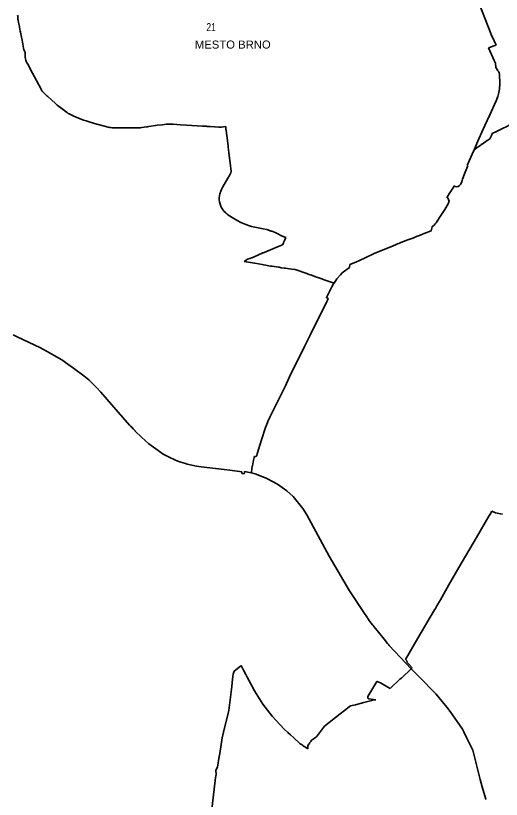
# Model space of a CAD drawing. Extents: x -610940 to -588976, y -1170376 to -1149800.
# Drawn here: x -599073 to -597562, y -1163066 to -1160628 of the extents above; entities that cross this region are included whole.
import ezdxf

# ---------------------------------------------------------------- set-up
doc = ezdxf.new("R2010")
doc.units = 0
doc.header["$LTSCALE"] = 10
doc.layers.add('54', color=7, linetype='Continuous', lineweight=35)
doc.layers.add('55', color=7, linetype='Continuous')
doc.layers.add('56', color=7, linetype='Continuous')

msp = doc.modelspace()

# ---------------------------------------------------------------- linework, layer by layer
at = {"layer": '54'}
for p, q in [((-597594.88, -1160683.07), (-597668.25, -1160495.45)), ((-599066.41, -1160629.92), (-599066.9, -1160626.17)), ((-599066.35, -1160633.96), (-599066.41, -1160629.92)), ((-599066.06, -1160638.29), (-599066.35, -1160633.96)), ((-599065.55, -1160642.13), (-599066.06, -1160638.29)), ((-599064.01, -1160649.25), (-599065.55, -1160642.13)), ((-599062.11, -1160657.95), (-599064.01, -1160649.25)), ((-599061.45, -1160661.37), (-599062.11, -1160657.95)), ((-599061.2, -1160663.36), (-599061.45, -1160661.37)), ((-599061.2, -1160663.36), (-599058.69, -1160676.02)), ((-599058.06, -1160679.43), (-599058.69, -1160676.02)), ((-599058.06, -1160679.43), (-599054.94, -1160694.74)), ((-599053.2, -1160704.32), (-599054.94, -1160694.74)), ((-599048.46, -1160728.59), (-599053.2, -1160704.32)), ((-597599.24, -1160726.56), (-597590.59, -1160723.51)), ((-597590.59, -1160723.51), (-597588.74, -1160722.86)), ((-597588.74, -1160722.86), (-597578.55, -1160719.28)), ((-599045.09, -1160738.12), (-599046.58, -1160735.24)), ((-599043.25, -1160742.45), (-599045.09, -1160738.12)), ((-599043.48, -1160750.77), (-599043.22, -1160747.53)), ((-599043.22, -1160747.53), (-599043.25, -1160742.45)), ((-597602.26, -1160727.62), (-597599.24, -1160726.56)), ((-599043.73, -1160755.78), (-599043.48, -1160750.77)), ((-599043.48, -1160758.32), (-599043.73, -1160755.78)), ((-599041.47, -1160766.34), (-599043.48, -1160758.32)), ((-599041.47, -1160766.34), (-599038.86, -1160772.13)), ((-599036.82, -1160776.06), (-599038.86, -1160772.13)), ((-599035.61, -1160778.39), (-599036.82, -1160776.06)), ((-599020.75, -1160807.03), (-599035.61, -1160778.39)), ((-599020.75, -1160807.03), (-599008.15, -1160829.7)), ((-599006.87, -1160832.11), (-599008.15, -1160829.7)), ((-598993.88, -1160856.59), (-599006.87, -1160832.11)), ((-598992.68, -1160858.85), (-598993.88, -1160856.59)), ((-598991.16, -1160861.71), (-598992.68, -1160858.85)), ((-598989.61, -1160863.67), (-598991.16, -1160861.71)), ((-598979.64, -1160873.91), (-598989.61, -1160863.67)), ((-597569.78, -1160867.25), (-597573.07, -1160879.91)), ((-598974.58, -1160878.03), (-598979.64, -1160873.91)), ((-598972.51, -1160879.73), (-598974.58, -1160878.03)), ((-598961.61, -1160890.04), (-598972.51, -1160879.73)), ((-598949.57, -1160901.32), (-598961.61, -1160890.04)), ((-597578.35, -1160892.94), (-597573.07, -1160879.91)), ((-598943.73, -1160906.84), (-598949.57, -1160901.32)), ((-598928.76, -1160918.03), (-598943.73, -1160906.84)), ((-598920.37, -1160924.27), (-598928.76, -1160918.03)), ((-598919.86, -1160924.7), (-598920.37, -1160924.27)), ((-598919.34, -1160925.06), (-598919.86, -1160924.7)), ((-598915.25, -1160928.11), (-598919.34, -1160925.06)), ((-598913.16, -1160929.48), (-598915.25, -1160928.11)), ((-598910.7, -1160931.18), (-598913.16, -1160929.48)), ((-598909.25, -1160932.14), (-598910.7, -1160931.18)), ((-598909.25, -1160932.14), (-598906.96, -1160933.05)), ((-598827.31, -1160962.99), (-598844.53, -1160958.1)), ((-598785.6, -1160974.72), (-598827.31, -1160962.99)), ((-598616.44, -1160967.17), (-598632.33, -1160969.03)), ((-598604.62, -1160966), (-598616.44, -1160967.17)), ((-598595.76, -1160965.71), (-598604.62, -1160966)), ((-598582.8, -1160965.72), (-598595.76, -1160965.71)), ((-598560.6, -1160967.14), (-598582.8, -1160965.72)), ((-598541.24, -1160968.18), (-598560.6, -1160967.14)), ((-598751.6, -1160976.39), (-598758.82, -1160977.15)), ((-598714.94, -1160976.93), (-598751.6, -1160976.39)), ((-598706.76, -1160976.86), (-598714.94, -1160976.93)), ((-598701.3, -1160976.83), (-598706.76, -1160976.86)), ((-598701.3, -1160976.83), (-598699.53, -1160976.82)), ((-598695.09, -1160976.8), (-598699.53, -1160976.82)), ((-598684.29, -1160976.62), (-598695.09, -1160976.8)), ((-598680.17, -1160976.07), (-598684.29, -1160976.62)), ((-598666.2, -1160974.2), (-598680.17, -1160976.07)), ((-598662.52, -1160973.72), (-598666.2, -1160974.2)), ((-598658.71, -1160973.12), (-598662.52, -1160973.72)), ((-598651.76, -1160972.06), (-598658.71, -1160973.12)), ((-598651.29, -1160971.93), (-598651.76, -1160972.06)), ((-598637.78, -1160969.85), (-598651.29, -1160971.93)), ((-598632.33, -1160969.03), (-598637.78, -1160969.85)), ((-598491.86, -1160971.37), (-598541.24, -1160968.18)), ((-598482.05, -1160972.03), (-598491.86, -1160971.37)), ((-598479.64, -1160972.19), (-598482.05, -1160972.03)), ((-598479.38, -1160972.21), (-598479.64, -1160972.19)), ((-598467.53, -1160973.01), (-598477.17, -1160972.36)), ((-598441.23, -1160974.45), (-598467.53, -1160973.01)), ((-598439.2, -1160974.55), (-598441.23, -1160974.45)), ((-598433.56, -1160974.83), (-598439.2, -1160974.55)), ((-598432.71, -1160974.7), (-598433.56, -1160974.83)), ((-598419.88, -1160973.04), (-598432.71, -1160974.7)), ((-598419.39, -1160975.88), (-598419.88, -1160973.04)), ((-598418.8, -1160981.9), (-598419.39, -1160975.88)), ((-598418.52, -1160983.89), (-598418.8, -1160981.9)), ((-598417.4, -1160993.06), (-598418.52, -1160983.89)), ((-598415.42, -1161008.49), (-598417.4, -1160993.06)), ((-598412.4, -1161034.23), (-598415.42, -1161008.49)), ((-597605.17, -1161015.95), (-597605.87, -1161016.4)), ((-598412.05, -1161036.82), (-598412.4, -1161034.23)), ((-598409.66, -1161054.09), (-598412.05, -1161036.82)), ((-597638.31, -1161038.82), (-597646.84, -1161045.22)), ((-597625.39, -1161029.41), (-597638.31, -1161038.82)), ((-597625.07, -1161029.18), (-597625.39, -1161029.41)), ((-597622.45, -1161027.58), (-597625.07, -1161029.18)), ((-598409.43, -1161056.18), (-598409.66, -1161054.09)), ((-598406.02, -1161085.51), (-598409.43, -1161056.18)), ((-598402.71, -1161112.81), (-598406.02, -1161085.51)), ((-598403.72, -1161117.01), (-598402.71, -1161112.81)), ((-597666.62, -1161094.84), (-597674.32, -1161114.99)), ((-597668.64, -1161094.03), (-597666.62, -1161094.84)), ((-598428.16, -1161160.61), (-598412.8, -1161133.51)), ((-598412.8, -1161133.51), (-598408.02, -1161125.63)), ((-598408.02, -1161125.63), (-598403.83, -1161117.31)), ((-598403.83, -1161117.31), (-598403.72, -1161117.01)), ((-597674.32, -1161114.99), (-597682.74, -1161136.59)), ((-598432.71, -1161169.23), (-598428.16, -1161160.61)), ((-597705.96, -1161159.46), (-597709.02, -1161157.86)), ((-598438.75, -1161188.27), (-598437.72, -1161182.67)), ((-598437.72, -1161182.67), (-598434.79, -1161173.45)), ((-598434.79, -1161173.45), (-598432.71, -1161169.23)), ((-598439.53, -1161194.7), (-598438.75, -1161188.27)), ((-598439.46, -1161200.48), (-598439.53, -1161194.7)), ((-598439.31, -1161207.09), (-598439.46, -1161200.48)), ((-598436.29, -1161217.76), (-598439.31, -1161207.09)), ((-598433.46, -1161223.74), (-598436.29, -1161217.76)), ((-598430.06, -1161230.26), (-598433.46, -1161223.74)), ((-598425.02, -1161236.55), (-598430.06, -1161230.26)), ((-598419.57, -1161241.87), (-598425.02, -1161236.55)), ((-598415.03, -1161245.67), (-598419.57, -1161241.87)), ((-598410.36, -1161249.19), (-598415.03, -1161245.67)), ((-598408, -1161250.49), (-598410.36, -1161249.19)), ((-598399.55, -1161255.76), (-598408, -1161250.49)), ((-598381.81, -1161266.18), (-598399.55, -1161255.76)), ((-598372.79, -1161270.99), (-598381.81, -1161266.18)), ((-598356.77, -1161277.36), (-598372.79, -1161270.99)), ((-598345.28, -1161281.54), (-598356.77, -1161277.36)), ((-598339.08, -1161283.42), (-598345.28, -1161281.54)), ((-598328.7, -1161286), (-598339.08, -1161283.42)), ((-598318.55, -1161287.95), (-598328.7, -1161286)), ((-598302.68, -1161291.04), (-598318.55, -1161287.95)), ((-598291.51, -1161293.62), (-598302.68, -1161291.04)), ((-598277.82, -1161297.99), (-598291.51, -1161293.62)), ((-598276.21, -1161298.8), (-598277.82, -1161297.99)), ((-598266.17, -1161303.05), (-598276.21, -1161298.8)), ((-598257.7, -1161307.04), (-598266.17, -1161303.05)), ((-598246.13, -1161312.49), (-598257.7, -1161307.04)), ((-598232.89, -1161318.61), (-598246.13, -1161312.49)), ((-598239.72, -1161334.14), (-598235.75, -1161325.87)), ((-598235.75, -1161325.87), (-598235.54, -1161325.32)), ((-598235.54, -1161325.32), (-598232.89, -1161318.61)), ((-598280.61, -1161356.28), (-598287.51, -1161359.22)), ((-598280.61, -1161356.28), (-598280.13, -1161356.14)), ((-598265.6, -1161350.06), (-598280.13, -1161356.14)), ((-598265.6, -1161350.06), (-598258.04, -1161346.97)), ((-598258.04, -1161346.97), (-598250.56, -1161343.85)), ((-598245.9, -1161341.95), (-598250.56, -1161343.85)), ((-598245.9, -1161341.95), (-598243.24, -1161340.68)), ((-598243.24, -1161340.68), (-598242.17, -1161339.71)), ((-598242.17, -1161339.71), (-598239.89, -1161334.82)), ((-598239.89, -1161334.82), (-598239.72, -1161334.14)), ((-597898.48, -1161343.76), (-597957.95, -1161368.31)), ((-598344.42, -1161383.07), (-598339.84, -1161381.57)), ((-598339.84, -1161381.57), (-598338, -1161380.97)), ((-598338, -1161380.97), (-598336.13, -1161380.24)), ((-598336.13, -1161380.24), (-598333.04, -1161379.16)), ((-598333.04, -1161379.16), (-598304.34, -1161366.26)), ((-598304.34, -1161366.26), (-598303.43, -1161365.96)), ((-598303.43, -1161365.96), (-598300.2, -1161364.58)), ((-598300.2, -1161364.58), (-598298.43, -1161363.84)), ((-598298.43, -1161363.84), (-598289.81, -1161360.2)), ((-598287.51, -1161359.22), (-598289.81, -1161360.2)), ((-598362.34, -1161392.74), (-598360.85, -1161391.58)), ((-598356.07, -1161393.6), (-598362.34, -1161392.74)), ((-598360.85, -1161391.58), (-598360.44, -1161391.82)), ((-598360.44, -1161391.82), (-598356.22, -1161388.78)), ((-598356.52, -1161388.45), (-598354.77, -1161387.14)), ((-598356.22, -1161388.78), (-598356.52, -1161388.45)), ((-598355.02, -1161393.73), (-598356.07, -1161393.6)), ((-598335.8, -1161397.11), (-598355.02, -1161393.73)), ((-598354.77, -1161387.14), (-598351.73, -1161385.95)), ((-598351.73, -1161385.95), (-598344.42, -1161383.07)), ((-598302.37, -1161403.12), (-598306.73, -1161402.37)), ((-598302.37, -1161403.12), (-598294.34, -1161404.4)), ((-598291.13, -1161404.91), (-598294.34, -1161404.4)), ((-598279.9, -1161406.94), (-598291.13, -1161404.91)), ((-598275.47, -1161407.46), (-598279.9, -1161406.94)), ((-598274.71, -1161407.57), (-598275.47, -1161407.46)), ((-598255.68, -1161410.48), (-598274.71, -1161407.57)), ((-598237.41, -1161413.2), (-598246.09, -1161412.28)), ((-598233.16, -1161413.52), (-598237.41, -1161413.2)), ((-598214.91, -1161416.32), (-598233.16, -1161413.52)), ((-598203.69, -1161418.04), (-598214.91, -1161416.32)), ((-598164.3, -1161431.63), (-598203.69, -1161418.04)), ((-598163.89, -1161431.89), (-598164.3, -1161431.63)), ((-598153.04, -1161435.74), (-598163.89, -1161431.89)), ((-598142.48, -1161439.35), (-598149.9, -1161436.71)), ((-598137.26, -1161441.06), (-598142.48, -1161439.35)), ((-598120.77, -1161446.88), (-598126.59, -1161444.89)), ((-598112.95, -1161449.52), (-598120.77, -1161446.88)), ((-598107.02, -1161451.62), (-598112.95, -1161449.52)), ((-598082.65, -1161460.09), (-598107.02, -1161451.62)), ((-598089.02, -1161471.3), (-598083.94, -1161462.19)), ((-598082.65, -1161460.09), (-598083.94, -1161462.19)), ((-598102.06, -1161511.05), (-598105.1, -1161517.25)), ((-599080.75, -1161621.2), (-599065.94, -1161628.12)), ((-599065.94, -1161628.12), (-598998.09, -1161660.51)), ((-598998.09, -1161660.51), (-598974.99, -1161672.34)), ((-598974.99, -1161672.34), (-598953.07, -1161685.05)), ((-598953.07, -1161685.05), (-598929.76, -1161698.95)), ((-598929.76, -1161698.95), (-598910.52, -1161712.03)), ((-598910.52, -1161712.03), (-598888.91, -1161727.38)), ((-598888.91, -1161727.38), (-598861.19, -1161748.52)), ((-598861.19, -1161748.52), (-598845.68, -1161761.08)), ((-598845.68, -1161761.08), (-598825.17, -1161781.28)), ((-598821.65, -1161784.92), (-598825.17, -1161781.28)), ((-598821.65, -1161784.92), (-598808.06, -1161799.42)), ((-598808.06, -1161799.42), (-598788.14, -1161822.37)), ((-598788.14, -1161822.37), (-598718.78, -1161901.85)), ((-598718.78, -1161901.85), (-598718.44, -1161902.25)), ((-598718.44, -1161902.25), (-598718.11, -1161902.63)), ((-598703.84, -1161917.32), (-598701.26, -1161919.92)), ((-598293.13, -1161902.29), (-598295.82, -1161909.22)), ((-598701.26, -1161919.92), (-598700.98, -1161920.26)), ((-598700.98, -1161920.26), (-598681.1, -1161939.74)), ((-598681.1, -1161939.74), (-598658.35, -1161959.86)), ((-598658.35, -1161959.86), (-598630.16, -1161981.32)), ((-598630.16, -1161981.32), (-598613.97, -1161991.76)), ((-598613.97, -1161991.76), (-598595.97, -1162001.6)), ((-598595.97, -1162001.6), (-598578.01, -1162010.1)), ((-598578.01, -1162010.1), (-598568.51, -1162013.74)), ((-598559.34, -1162017.25), (-598568.51, -1162013.74)), ((-598330.34, -1161999.7), (-598330.87, -1162001.34)), ((-598330.42, -1161999.13), (-598330.34, -1161999.7)), ((-598330.42, -1161999.13), (-598329.17, -1161999.67)), ((-598327.84, -1161999.87), (-598329.17, -1161999.67)), ((-598327.84, -1161999.87), (-598326.6, -1161999.69)), ((-598326.6, -1161999.69), (-598325.46, -1161999.37)), ((-598324.63, -1161998.8), (-598325.46, -1161999.37)), ((-598324.63, -1161998.8), (-598323.76, -1161998.16)), ((-598323.76, -1161998.16), (-598323.03, -1161997.13)), ((-598322.64, -1161996.12), (-598323.03, -1161997.13)), ((-598559.34, -1162017.25), (-598544.7, -1162021.54)), ((-598539.94, -1162022.93), (-598544.7, -1162021.54)), ((-598539.94, -1162022.93), (-598510.84, -1162029.39)), ((-598510.84, -1162029.39), (-598496.11, -1162031.78)), ((-598496.11, -1162031.78), (-598406.5, -1162041.96)), ((-598406.5, -1162041.96), (-598368.98, -1162046.88)), ((-598369.12, -1162047.84), (-598369.89, -1162052.52)), ((-598369.89, -1162052.52), (-598362.27, -1162053.87)), ((-598369.04, -1162047.3), (-598369.12, -1162047.84)), ((-598368.98, -1162046.88), (-598369.04, -1162047.3)), ((-598362.27, -1162053.87), (-598361.52, -1162048.88)), ((-598361.52, -1162048.88), (-598361.43, -1162048.3)), ((-598361.43, -1162048.3), (-598361.36, -1162047.8)), ((-598361.36, -1162047.8), (-598361.18, -1162046.53)), ((-598361.18, -1162046.53), (-598340.53, -1162050.35)), ((-598340.45, -1162049.97), (-598340.53, -1162050.35)), ((-597593.41, -1162172.45), (-597591.66, -1162169.43)), ((-597591.66, -1162169.43), (-597580.73, -1162174.42)), ((-597580.73, -1162174.42), (-597580.77, -1162174.72)), ((-598097.78, -1162309.19), (-598034.29, -1162417.39)), ((-597757.93, -1162455.57), (-597756.73, -1162453.43)), ((-597751.94, -1162445.17), (-597756.73, -1162453.43)), ((-597763.13, -1162464.52), (-597757.93, -1162455.57)), ((-597773.31, -1162482.07), (-597821.58, -1162564.89)), ((-597961.3, -1162525.5), (-597954.6, -1162533.5)), ((-597859.96, -1162631.03), (-597821.58, -1162564.89)), ((-597855.03, -1162636.18), (-597856.1, -1162639.64)), ((-597849.98, -1162646.15), (-597856.1, -1162639.64)), ((-597839.47, -1162657.18), (-597849.98, -1162646.15)), ((-598396.11, -1162676.68), (-598393.2, -1162667.95)), ((-598393.2, -1162667.95), (-598373.94, -1162652.35)), ((-598373.94, -1162652.35), (-598371.38, -1162650.24)), ((-598371.38, -1162650.24), (-598363.92, -1162664.78)), ((-598357.33, -1162677.85), (-598363.92, -1162664.78)), ((-597867.03, -1162683.19), (-597848.21, -1162665.42)), ((-597848.21, -1162665.42), (-597842.74, -1162660.07)), ((-598396.11, -1162676.68), (-598398.15, -1162692.85)), ((-598353.06, -1162686.32), (-598357.33, -1162677.85)), ((-598347.98, -1162695.71), (-598353.06, -1162686.32)), ((-598330.19, -1162728.59), (-598347.98, -1162695.71)), ((-597908.11, -1162721.5), (-597877.92, -1162692.82)), ((-597877.92, -1162692.82), (-597877.74, -1162692.74)), ((-597877.74, -1162692.74), (-597875.19, -1162690.71)), ((-597875.19, -1162690.71), (-597873.21, -1162689)), ((-597873.21, -1162689), (-597867.03, -1162683.19)), ((-597977.15, -1162746.49), (-597949.32, -1162699.43)), ((-597949.32, -1162699.43), (-597948.83, -1162699.65)), ((-597938.52, -1162704.22), (-597948.83, -1162699.65)), ((-598330.19, -1162728.59), (-598304.1, -1162770.27)), ((-597977.76, -1162751.42), (-597977.15, -1162746.49)), ((-598304.1, -1162770.27), (-598275.12, -1162807.77)), ((-598016.39, -1162771.94), (-597989.96, -1162765.29)), ((-597989.96, -1162765.29), (-597960.77, -1162758.18)), ((-597974.64, -1162753.6), (-597977.76, -1162751.42)), ((-597952.16, -1162756.86), (-597974.64, -1162753.6)), ((-597960.77, -1162758.18), (-597952.16, -1162756.86)), ((-598411.49, -1162797.71), (-598410.4, -1162790.07)), ((-598046.03, -1162786.56), (-598067.86, -1162803.46)), ((-598034.5, -1162777.64), (-598046.03, -1162786.56)), ((-598034.5, -1162777.64), (-598031.25, -1162775.8)), ((-598031.25, -1162775.8), (-598026.05, -1162774.27)), ((-598026.05, -1162774.27), (-598016.39, -1162771.94)), ((-597731.79, -1162778.94), (-597720.92, -1162792.47)), ((-597720.92, -1162792.47), (-597683.2, -1162847.84)), ((-598426.18, -1162857.33), (-598411.49, -1162797.71)), ((-598275.12, -1162807.77), (-598237.38, -1162848.22)), ((-598112.37, -1162838.49), (-598077.66, -1162811.09)), ((-598077.66, -1162811.09), (-598073.87, -1162808.11)), ((-598073.87, -1162808.11), (-598067.86, -1162803.46)), ((-598137.67, -1162871.26), (-598112.37, -1162838.49)), ((-598430.61, -1162874.56), (-598426.18, -1162857.33)), ((-598237.38, -1162848.22), (-598226.45, -1162858.19)), ((-598217.84, -1162865.92), (-598226.45, -1162858.19)), ((-598217.73, -1162866.02), (-598217.84, -1162865.92)), ((-598208.8, -1162874.17), (-598217.73, -1162866.02)), ((-597683.2, -1162847.84), (-597679.28, -1162855.81)), ((-597679.28, -1162855.81), (-597670.61, -1162873.35)), ((-598430.61, -1162874.56), (-598438.09, -1162923.19)), ((-598187.67, -1162893.45), (-598208.8, -1162874.17)), ((-598187.67, -1162893.45), (-598182.28, -1162897.03)), ((-598163.92, -1162898.96), (-598160.25, -1162893.03)), ((-598160.25, -1162893.03), (-598159.44, -1162892.11)), ((-598159.44, -1162892.11), (-598158.52, -1162890.58)), ((-598158.52, -1162890.58), (-598155.17, -1162885.83)), ((-598155.17, -1162885.83), (-598153.45, -1162883.38)), ((-598153.45, -1162883.38), (-598147.19, -1162878.93)), ((-598143.42, -1162875.92), (-598147.19, -1162878.93)), ((-598143.42, -1162875.92), (-598137.67, -1162871.26)), ((-597650.96, -1162912.75), (-597670.61, -1162873.35)), ((-598182.28, -1162897.03), (-598179.2, -1162899.05)), ((-598179.2, -1162899.05), (-598175.28, -1162901.64)), ((-598175.28, -1162901.64), (-598171.61, -1162904.06)), ((-598171.61, -1162904.06), (-598163.68, -1162909.29)), ((-598163.68, -1162909.29), (-598163.92, -1162898.96)), ((-598450.14, -1162975.68), (-598444.66, -1162965.91)), ((-598450.4, -1162994.49), (-598448.81, -1162989.08)), ((-598448.81, -1162989.08), (-598450.14, -1162975.68)), ((-598464.95, -1163115.09), (-598451.06, -1162998.14)), ((-598451.06, -1162998.14), (-598450.4, -1162994.49)), ((-597613.73, -1163055.42), (-597622.06, -1163027.57)), ((-597613.73, -1163055.42), (-597610.45, -1163066.2)), ((-597610.45, -1163066.2), (-597609.87, -1163066.21))]:
    msp.add_line(p, q, dxfattribs=at)
for points in [[(-597578.55, -1160719.28), (-597579.64, -1160717.36), (-597584.97, -1160706.4), (-597593.42, -1160686.94), (-597594.88, -1160683.07)], [(-599046.58, -1160735.24), (-599047.83, -1160732.94), (-599048.46, -1160728.59)], [(-597573.42, -1160798.47), (-597579.42, -1160788.89), (-597580.84, -1160775.86), (-597584.35, -1160767.56), (-597584.67, -1160767.62), (-597602.26, -1160727.62)], [(-597566.44, -1160839.04), (-597567.97, -1160810.76), (-597569.04, -1160806), (-597570.32, -1160803.17), (-597574.28, -1160798.64), (-597573.42, -1160798.47)], [(-597569.78, -1160867.25), (-597567.88, -1160856.49), (-597566.44, -1160839.04)], [(-597646.84, -1161045.22), (-597632.55, -1161011.51), (-597613.84, -1160969.67), (-597598.47, -1160936.67), (-597578.35, -1160892.94)], [(-598906.96, -1160933.05), (-598895.71, -1160938.43), (-598882.27, -1160944.58), (-598868.94, -1160950.17), (-598861.84, -1160952.77), (-598854.03, -1160955.29), (-598844.53, -1160958.1)], [(-597590.45, -1160994.53), (-597577.12, -1160988.21), (-597560.42, -1160980.25), (-597543.22, -1160971.24), (-597536.36, -1160967.58), (-597532.3, -1160965.69)], [(-598785.6, -1160974.72), (-598781.38, -1160975.6), (-598777.04, -1160976.34), (-598772.44, -1160976.88), (-598767.68, -1160977.08), (-598758.82, -1160977.15)], [(-598477.17, -1160972.36), (-598477.47, -1160972.34), (-598479.38, -1160972.21)], [(-597598.12, -1161011.4), (-597604.48, -1161015.5), (-597605.17, -1161015.95)], [(-597590.45, -1160994.53), (-597593.01, -1161001.12), (-597597.5, -1161011.03), (-597598.12, -1161011.4)], [(-597605.87, -1161016.4), (-597610.04, -1161019.02), (-597618.14, -1161024.28), (-597622.34, -1161027.51), (-597622.45, -1161027.58)], [(-597646.84, -1161045.22), (-597652.57, -1161058.4), (-597660.89, -1161077.01), (-597668.64, -1161094.03)], [(-597682.74, -1161136.59), (-597684.2, -1161140.33), (-597688.72, -1161152.28)], [(-597709.02, -1161157.86), (-597709.79, -1161159.14), (-597712.54, -1161163.28)], [(-597696.88, -1161159.17), (-597701.08, -1161160.03), (-597705.96, -1161159.46)], [(-597688.72, -1161152.28), (-597692.15, -1161156.42), (-597696.88, -1161159.17)], [(-597722.76, -1161179.19), (-597723.23, -1161179.93), (-597727.86, -1161187.25)], [(-597717.59, -1161171.2), (-597718.25, -1161172.16), (-597718.45, -1161172.51), (-597722.37, -1161178.65), (-597722.76, -1161179.19)], [(-597712.54, -1161163.28), (-597717.37, -1161170.85), (-597717.59, -1161171.2)], [(-597727.86, -1161187.25), (-597731.05, -1161192.26), (-597731.48, -1161192.94), (-597728.43, -1161195.13), (-597724.89, -1161205.18), (-597727.77, -1161213.58)], [(-597752, -1161252.65), (-597738.38, -1161230.68), (-597727.77, -1161213.58)], [(-597752, -1161252.65), (-597761.37, -1161267.74), (-597764.66, -1161272.52), (-597767.6, -1161275.85), (-597771.54, -1161279.99), (-597777.8, -1161284.41), (-597780.88, -1161297.89), (-597802.3, -1161305.91)], [(-597802.3, -1161305.91), (-597807.89, -1161308.1), (-597811.66, -1161309.58), (-597812.95, -1161310.08), (-597816.68, -1161311.55), (-597820.41, -1161313.01), (-597824.13, -1161314.46), (-597827.85, -1161315.92), (-597831.58, -1161317.4), (-597832.77, -1161317.85), (-597841.14, -1161321.11), (-597853.31, -1161325.85), (-597879.95, -1161336.22), (-597880.3, -1161336.36)], [(-597885.37, -1161338.33), (-597889.83, -1161340.19), (-597891.97, -1161341.07), (-597898.48, -1161343.76)], [(-597880.3, -1161336.36), (-597883.76, -1161337.66), (-597885.37, -1161338.33)], [(-597957.95, -1161368.31), (-597987.58, -1161381.97), (-598015.31, -1161394.35), (-598033.26, -1161402.39)], [(-598306.73, -1161402.37), (-598329.44, -1161398.32), (-598335.8, -1161397.11)], [(-598033.26, -1161402.39), (-598034.27, -1161410.71), (-598034.41, -1161411.84)], [(-598246.09, -1161412.28), (-598246.92, -1161412.12), (-598253.83, -1161410.83), (-598255.68, -1161410.48)], [(-598034.41, -1161411.84), (-598057.25, -1161427.72), (-598062.98, -1161433.84), (-598073.45, -1161447.02), (-598082.65, -1161460.09)], [(-598149.9, -1161436.71), (-598152.17, -1161435.86), (-598153.04, -1161435.74)], [(-598126.59, -1161444.89), (-598136.59, -1161441.26), (-598137.26, -1161441.06)], [(-598089.02, -1161471.3), (-598090.32, -1161473.18), (-598106.37, -1161505.05), (-598100.5, -1161508.2), (-598102.06, -1161511.05)], [(-598105.1, -1161517.25), (-598112.6, -1161532.63), (-598119.49, -1161546.62)], [(-598119.49, -1161546.62), (-598157.77, -1161624.23), (-598174.3, -1161657.75)], [(-598174.3, -1161657.75), (-598220.86, -1161751.71), (-598230.6, -1161772.67), (-598233.81, -1161779.13), (-598241.25, -1161794.31), (-598244.3, -1161800.11)], [(-598244.3, -1161800.11), (-598282.73, -1161877.6), (-598288.74, -1161890.9), (-598293.13, -1161902.29)], [(-598718.11, -1161902.63), (-598715.55, -1161905.25), (-598712.14, -1161908.77), (-598707.37, -1161913.69), (-598703.84, -1161917.32)], [(-598295.82, -1161909.22), (-598296.97, -1161912.35), (-598308.6, -1161948.05), (-598321.28, -1161991.38), (-598322.64, -1161996.12)], [(-598331.27, -1162003.07), (-598333.11, -1162011.38), (-598334.46, -1162017.5), (-598335.19, -1162021.63), (-598335.31, -1162022.24), (-598336.43, -1162028.17), (-598336.52, -1162028.66), (-598336.81, -1162030.49), (-598336.9, -1162030.98), (-598338.01, -1162036.88), (-598338.1, -1162037.34), (-598338.13, -1162037.54), (-598338.44, -1162039.26), (-598338.47, -1162039.46), (-598339.66, -1162046.05), (-598339.73, -1162046.53), (-598340.45, -1162049.97)], [(-598330.87, -1162001.34), (-598331.09, -1162002.39), (-598331.27, -1162003.07)], [(-598340.53, -1162050.35), (-598338.89, -1162050.74), (-598324.91, -1162054), (-598291.34, -1162067.48), (-598258.47, -1162085.36), (-598229.5, -1162106.51), (-598210.14, -1162123.52), (-598180.08, -1162161.31), (-598167.31, -1162180.83), (-598097.78, -1162309.19)], [(-597694.06, -1162345.28), (-597639.81, -1162251.76), (-597601.09, -1162185.6), (-597595.4, -1162175.88)], [(-597595.4, -1162175.88), (-597593.89, -1162173.28), (-597593.41, -1162172.45)], [(-597580.77, -1162174.72), (-597564.55, -1162177.62), (-597558.11, -1162178.77)], [(-597751.94, -1162445.17), (-597725.37, -1162399.31), (-597694.06, -1162345.28)], [(-598034.29, -1162417.39), (-597985.91, -1162490.87), (-597984.78, -1162492.56), (-597971.28, -1162512.78), (-597962.77, -1162523.33), (-597961.3, -1162525.5)], [(-597773.31, -1162482.07), (-597770.37, -1162477.02), (-597767.52, -1162472.09), (-597763.13, -1162464.52)], [(-597954.6, -1162533.5), (-597948.44, -1162541.09), (-597926.47, -1162568.32)], [(-597926.47, -1162568.32), (-597916.03, -1162581.31), (-597912.7, -1162585.51), (-597911.22, -1162587.27), (-597842.74, -1162660.07)], [(-597855.03, -1162636.18), (-597857.28, -1162633.76), (-597859.96, -1162631.03)], [(-597842.74, -1162660.07), (-597842.44, -1162659.8), (-597840.19, -1162657.82), (-597839.47, -1162657.18)], [(-597842.74, -1162660.07), (-597818.92, -1162684.01), (-597764.44, -1162738.76)], [(-598398.15, -1162692.85), (-598400.94, -1162715.02), (-598410.4, -1162790.07)], [(-597938.52, -1162704.22), (-597915.38, -1162717.37), (-597908.11, -1162721.5)], [(-597764.44, -1162738.76), (-597755.3, -1162750), (-597731.79, -1162778.94)], [(-597622.06, -1163027.57), (-597627.85, -1163004.23), (-597650.96, -1162912.75)], [(-598438.09, -1162923.19), (-598439.61, -1162933.06), (-598444.66, -1162965.91)]]:
    msp.add_lwpolyline(points, dxfattribs=at)

# ---------------------------------------------------------------- texts
at = {"layer": '55', "width": 1.05}
msp.add_text('MESTO BRNO', height=25, dxfattribs=at).set_placement((-598515.58, -1160730.31))
at = {"layer": '56', "width": 0.8}
msp.add_text('21 ', height=25, dxfattribs=at).set_placement((-598479.85, -1160675.99))

doc.saveas('drawing.dxf')
